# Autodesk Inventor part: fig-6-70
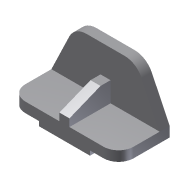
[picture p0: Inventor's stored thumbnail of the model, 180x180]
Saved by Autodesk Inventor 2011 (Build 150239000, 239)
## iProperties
Shininess: 77.0
Length Units: 11269
Angle Units: 11279
Time Units: 11290
Mass Units: 11283
Length Display Precision: 3
Angle Display Precision: 2
Created: 2001-12
Part Number: fig-6-70
Document SubType Name: Modeling
Designer: Renu Muthoo
Density: 1 g/cm^3
Density: 0.0
Volumn: 0.0
Area: 0.0
PropertySet Name: Model Information
Control State: 0
Master: False
Checked Out: False
Author: Renu Muthoo
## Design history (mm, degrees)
sketch "Sketch2"
  geometry: L1 (-67.219, 19.116)-(148.781, 19.116); L2 (148.781, 19.116)-(148.781, -0.884); L3 (-67.219, -0.884)-(-67.219, 19.116); L4 (-10.219, -0.884)-(-10.219, -9.884); L5 (-10.219, -9.884)-(91.781, -9.884); L6 (91.781, -9.884)-(91.781, -0.884); L7 (148.781, -0.884)-(91.781, -0.884); L8 (-10.219, -0.884)-(-67.219, -0.884)
  constraints: 16 end point, 5 parallel, 4 perpendicular, 2 equal length, 1 horizontal
  dimensions: "d0" = 102 distance of L4.end L5.end; "d1" = 57 distance of L4.start L3.start; "d2" = 29 distance between parallel lines of L1 L5; "d3" = 20 distance of L1.end L2.end
extrude "Extrusion1" new body sketch "Sketch2" distance "d4" = 102; taper "d5" = 0 deg
sketch "Sketch3"
  geometry: L1 (67.219, -19.116)-(-148.781, -19.116) reference; L2 (67.219, -19.116)-(31.475, -93.564); L3 (-2.781, -115.116)-(-78.781, -115.116); L4 (-113.038, -93.564)-(-148.781, -19.116); A1 r 38 centre (-2.781, -77.116) between (-2.781, -115.116) and (31.475, -93.564); A2 r 38 centre (-78.781, -77.116) between (-113.038, -93.564) and (-78.781, -115.116)
  constraints: 6 end point, 4 point on circle, 4 tangent, 2 centre point, 1 equal length, 1 equal radius, 1 parallel
  dimensions: "d6" = 96 distance between parallel lines of L3 L1; "d7" = 38 radius of A1; "d8" = 76 distance of A2.centre A1.centre
extrude "Extrusion2" join sketch "Sketch3" distance "d9" = 20; taper "d10" = 0 deg
fillet "Fillet1" dims "d11" = 30
workplane "Work Plane1"
sketch "Sketch7"
  geometry: L1 (0, -82)-(-15, -82); L2 (-15, -82)-(-40, -20); L3 (-40, -20)-(-40, 0); L4 (0, -82)-(20, -82) reference; L5 (0, 0)-(-74.447, 0) reference
  constraints: 6 end point, 2 point on line, 1 horizontal, 1 perpendicular
  dimensions: "d32" = 20 distance of L2.end L3.end; "d33" = 15 distance of L1.start L1.end; "d34" = 40 distance of L5.start L3.end
feature "Rib4" sketch "Sketch7" dims "d55" = 1, "d56" = 20, "d57" = 0
body "Solid1"
other parameters: "d12" = -108
